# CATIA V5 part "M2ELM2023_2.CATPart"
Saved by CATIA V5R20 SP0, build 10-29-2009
Part number: Part1
Bounding box of the stored display mesh (mm): x -59.975 to 59.975, y 0 to 103.923, z -59.975 to 59.975
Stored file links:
  E:\0 Pedagogie\01 Hamma Lakhdar University\0Pedagogie\2023 2024\M2ELM CFAO\Travail a domicile 3\M2ELM2023_2.CATPart
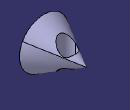
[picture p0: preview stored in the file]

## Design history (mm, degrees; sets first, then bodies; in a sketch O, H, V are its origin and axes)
Body1 (main body)
  Sketch1 on xy-plane, origin (0, 0, 0), H (1, 0, 0), V (0, 1, 0)
    line L1 (0, 0) -> (60, 0)
    line L2 (60, 0) -> (0, 103.923)
    point P2 (0, 103.923)
    line L3 (0, 103.923) -> (0, 0)
    length L1 = 60
    angle L2 L1 = 60
    horizontal: L1 H
    coincidence: P2 V
    vertical: L3 V
  Shaft1: profile Sketch1, axis Sketch1.L3, angle 360
  Sketch2 on xy-plane, origin (0, 0, 0), H (1, 0, 0), V (0, 1, 0)
    circle A1 centre (0, 58) radius 20
    point P1 (0, 58)
    coincidence: P1 V
  Pocket1: profile Sketch2, direction (0, 0, -1), length 53, mirrored extent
